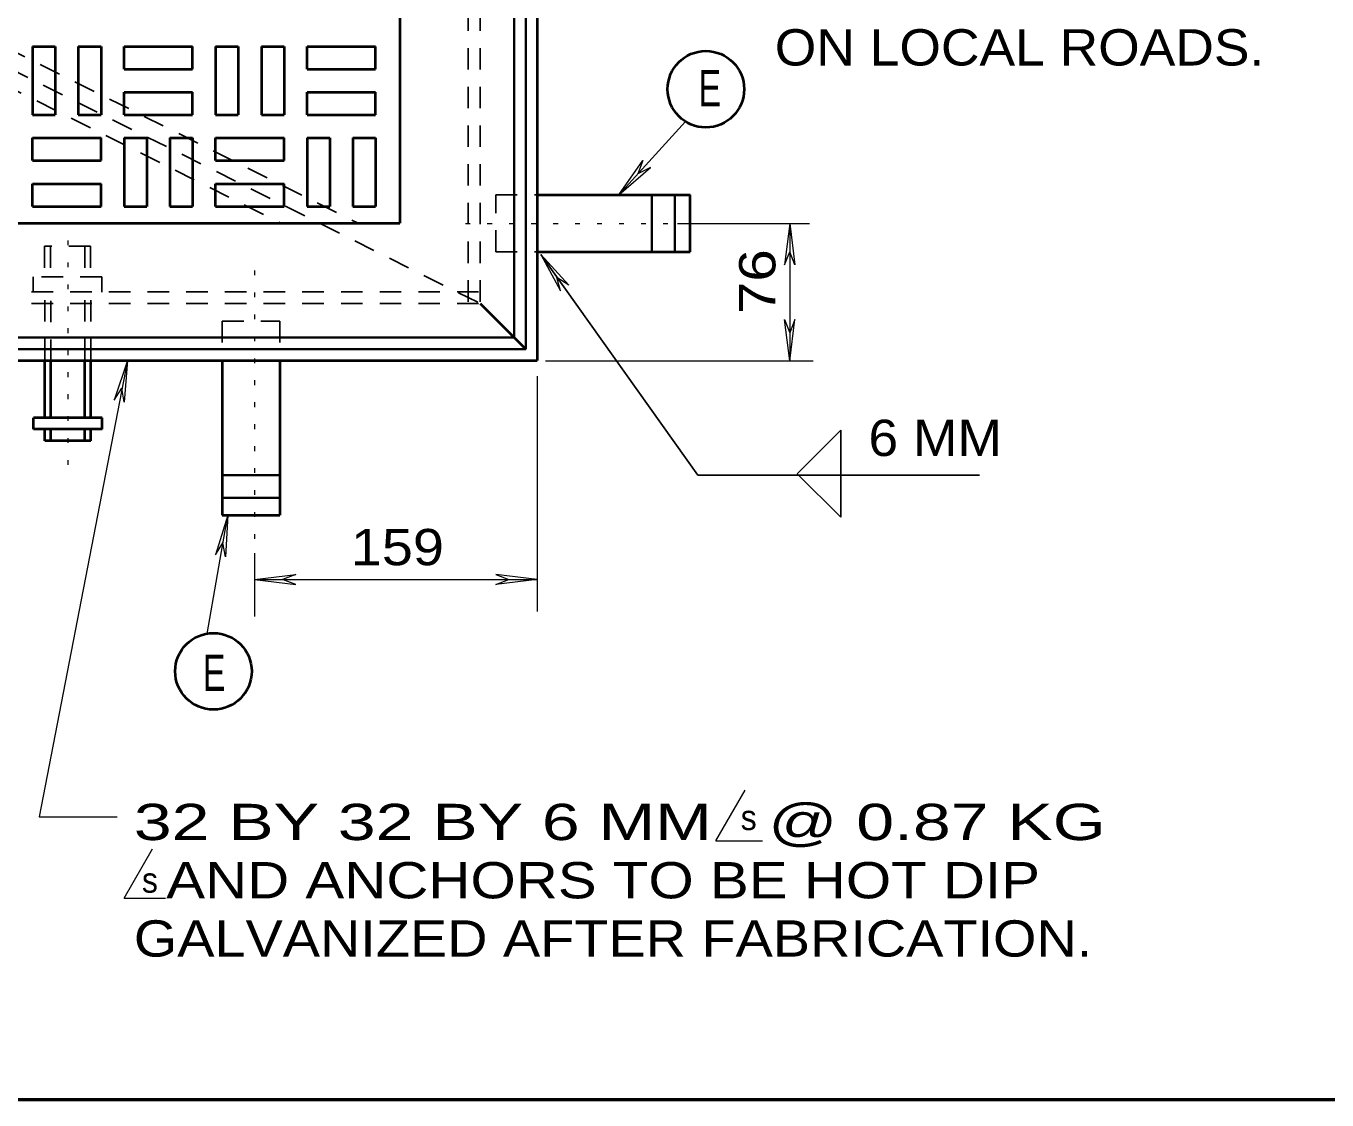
# Model space of a CAD drawing. Extents: x 312583 to 312854, y 144419 to 144597.
# Drawn here: x 312714.2 to 312741.44, y 144527.44 to 144549.93 of the extents above; entities that cross this region are included whole.
import ezdxf

# ---------------------------------------------------------------- set-up
doc = ezdxf.new("R2010")
doc.units = 0
doc.header["$LTSCALE"] = 0.3
doc.linetypes.add('DOTTED', pattern=[1.5, 0.3, -1.2])
doc.linetypes.add('SHORT_DASHED', pattern=[2.7, 1.5, -1.2])
doc.layers.add('1', color=7, linetype='Continuous', lineweight=40)
doc.layers.add('2', color=7, linetype='Continuous', lineweight=13)

msp = doc.modelspace()

# ---------------------------------------------------------------- linework, layer by layer
at = {"layer": '1', "linetype": 'SHORT_DASHED', "lineweight": 25}
for p, q in [((312689.2049, 144561.3686), (312723.7049, 144544.1186)), ((312707.2522, 144552.7436), (312721.1519, 144545.7976)), ((312723.4595, 144552.7053), (312723.4595, 144544.1186)), ((312706.4549, 144552.3449), (312719.5419, 144545.7976)), ((312724.0345, 144545.1996), (312724.0345, 144546.3956)), ((312724.0345, 144546.3956), (312724.9009, 144546.3956)), ((312715.5475, 144545.3146), (312714.5892, 144545.3146)), ((312714.5892, 144545.3146), (312714.5892, 144544.6783)), ((312714.7119, 144545.3146), (312714.7119, 144544.6783)), ((312715.4325, 144545.3146), (312715.4325, 144544.6783)), ((312715.5475, 144545.3146), (312715.5475, 144544.6783)), ((312724.0345, 144545.1996), (312724.9009, 144545.1996)), ((312714.3515, 144544.6783), (312714.3515, 144544.3563)), ((312715.7852, 144544.6783), (312714.3515, 144544.6783)), ((312715.7852, 144544.6783), (312715.7852, 144544.3563)), ((312689.2049, 144544.3639), (312723.7049, 144544.3639)), ((312714.5969, 144542.9303), (312714.5969, 144544.3639)), ((312714.7195, 144542.9149), (312714.7195, 144544.3639)), ((312715.4325, 144542.9303), (312715.4325, 144544.3639)), ((312715.5552, 144542.9303), (312715.5552, 144544.3639)), ((312718.3075, 144543.7506), (312719.5112, 144543.7506)), ((312718.3075, 144543.7506), (312718.3075, 144542.9149)), ((312719.5112, 144543.7506), (312719.5112, 144542.9303))]:
    msp.add_line(p, q, dxfattribs=at)
at = {"layer": '1'}
for p, q in [((312722.0259, 144559.6973), (312722.0259, 144545.7976)), ((312714.3362, 144549.5006), (312714.3362, 144548.0669)), ((312714.3362, 144549.5006), (312714.8115, 144549.5006)), ((312714.8115, 144549.5006), (312714.8115, 144548.0669)), ((312715.2945, 144549.5006), (312715.2945, 144548.0669)), ((312715.2945, 144549.5006), (312715.7699, 144549.5006)), ((312715.7699, 144549.5006), (312715.7699, 144548.0669)), ((312716.2529, 144549.5006), (312717.6865, 144549.5006)), ((312716.2529, 144549.0253), (312716.2529, 144549.5006)), ((312717.6865, 144549.0253), (312717.6865, 144549.5006)), ((312718.1695, 144549.5006), (312718.1695, 144548.0669)), ((312718.1695, 144549.5006), (312718.6449, 144549.5006)), ((312718.6449, 144549.5006), (312718.6449, 144548.0669)), ((312719.1279, 144549.5006), (312719.1279, 144548.0669)), ((312719.1279, 144549.5006), (312719.6032, 144549.5006)), ((312719.6032, 144549.5006), (312719.6032, 144548.0669)), ((312720.0862, 144549.5006), (312721.5199, 144549.5006)), ((312720.0862, 144549.0253), (312720.0862, 144549.5006)), ((312721.5199, 144549.0253), (312721.5199, 144549.5006)), ((312716.2529, 144549.0253), (312717.6865, 144549.0253)), ((312720.0862, 144549.0253), (312721.5199, 144549.0253)), ((312716.2529, 144548.5423), (312717.6865, 144548.5423)), ((312716.2529, 144548.0669), (312716.2529, 144548.5423)), ((312717.6865, 144548.0669), (312717.6865, 144548.5423)), ((312720.0862, 144548.5423), (312721.5199, 144548.5423)), ((312720.0862, 144548.0669), (312720.0862, 144548.5423)), ((312721.5199, 144548.0669), (312721.5199, 144548.5423)), ((312714.3362, 144548.0669), (312714.8115, 144548.0669)), ((312715.2945, 144548.0669), (312715.7699, 144548.0669)), ((312716.2529, 144548.0669), (312717.6865, 144548.0669)), ((312718.1695, 144548.0669), (312718.6449, 144548.0669)), ((312719.1279, 144548.0669), (312719.6032, 144548.0669)), ((312720.0862, 144548.0669), (312721.5199, 144548.0669)), ((312714.3362, 144547.5839), (312715.7699, 144547.5839)), ((312714.3362, 144547.1086), (312714.3362, 144547.5839)), ((312715.7699, 144547.1086), (312715.7699, 144547.5839)), ((312716.2529, 144547.5839), (312716.2529, 144546.1503)), ((312716.2529, 144547.5839), (312716.7282, 144547.5839)), ((312716.7282, 144547.5839), (312716.7282, 144546.1503)), ((312717.2112, 144547.5839), (312717.2112, 144546.1503)), ((312717.2112, 144547.5839), (312717.6865, 144547.5839)), ((312717.6865, 144547.5839), (312717.6865, 144546.1503)), ((312718.1695, 144547.5839), (312719.6032, 144547.5839)), ((312718.1695, 144547.1086), (312718.1695, 144547.5839)), ((312719.6032, 144547.1086), (312719.6032, 144547.5839)), ((312720.0862, 144547.5839), (312720.0862, 144546.1503)), ((312720.0862, 144547.5839), (312720.5615, 144547.5839)), ((312720.5615, 144547.5839), (312720.5615, 144546.1503)), ((312721.0445, 144547.5839), (312721.0445, 144546.1503)), ((312721.0445, 144547.5839), (312721.5199, 144547.5839)), ((312721.5199, 144547.5839), (312721.5199, 144546.1503)), ((312714.3362, 144547.1086), (312715.7699, 144547.1086)), ((312718.1695, 144547.1086), (312719.6032, 144547.1086)), ((312714.3362, 144546.6256), (312715.7699, 144546.6256)), ((312714.3362, 144546.1503), (312714.3362, 144546.6256)), ((312715.7699, 144546.1503), (312715.7699, 144546.6256)), ((312718.1695, 144546.6256), (312719.6032, 144546.6256)), ((312718.1695, 144546.1503), (312718.1695, 144546.6256)), ((312719.6032, 144546.1503), (312719.6032, 144546.6256)), ((312724.9009, 144546.3956), (312728.1055, 144546.3956)), ((312728.1055, 144545.1996), (312728.1055, 144546.3956)), ((312714.3362, 144546.1503), (312715.7699, 144546.1503)), ((312716.2529, 144546.1503), (312716.7282, 144546.1503)), ((312717.2112, 144546.1503), (312717.6865, 144546.1503)), ((312718.1695, 144546.1503), (312719.6032, 144546.1503)), ((312720.0862, 144546.1503), (312720.5615, 144546.1503)), ((312721.0445, 144546.1503), (312721.5199, 144546.1503)), ((312690.8762, 144545.7976), (312722.0259, 144545.7976)), ((312724.9009, 144545.1996), (312728.1055, 144545.1996)), ((312723.7049, 144544.1186), (312724.6632, 144543.1603)), ((312688.0012, 144542.9226), (312724.9009, 144542.9226)), ((312714.5969, 144541.7266), (312714.5969, 144542.9303)), ((312714.7195, 144541.7266), (312714.7195, 144542.9149)), ((312715.4325, 144541.7266), (312715.4325, 144542.9303)), ((312715.5552, 144541.7266), (312715.5552, 144542.9149)), ((312718.3075, 144542.9149), (312718.3075, 144539.6873)), ((312719.5112, 144542.9149), (312719.5112, 144539.6873)), ((312715.7929, 144541.7266), (312714.3592, 144541.7266)), ((312714.3592, 144541.4889), (312714.3592, 144541.7266)), ((312715.7929, 144541.4889), (312715.7929, 144541.7266)), ((312715.7929, 144541.4889), (312714.3592, 144541.4889)), ((312714.5969, 144541.2436), (312714.5969, 144541.4889)), ((312714.7195, 144541.2436), (312714.7195, 144541.4889)), ((312715.4325, 144541.2436), (312715.4325, 144541.4889)), ((312715.5552, 144541.2436), (312715.5552, 144541.4889)), ((312715.5552, 144541.2436), (312714.5969, 144541.2436)), ((312718.3075, 144539.6873), (312719.5112, 144539.6873))]:
    msp.add_line(p, q, dxfattribs=at)
at = {"layer": '1', "lineweight": 35}
for p, q in [((312724.4179, 144552.4906), (312724.4179, 144543.4056)), ((312727.3005, 144546.3956), (312727.3005, 144545.1996)), ((312727.7835, 144546.3956), (312727.7835, 144545.1996)), ((312688.4842, 144543.4056), (312724.4179, 144543.4056)), ((312688.2465, 144543.1603), (312724.6632, 144543.1603)), ((312718.3075, 144540.5229), (312719.5112, 144540.5229)), ((312718.3075, 144540.0476), (312719.5112, 144540.0476))]:
    msp.add_line(p, q, dxfattribs=at)
at = {"layer": '1', "linetype": 'DOTTED', "lineweight": 13}
for p, q in [((312723.3982, 144545.7899), (312727.8372, 144545.7899)), ((312715.0799, 144540.7376), (312715.0799, 144545.4756))]:
    msp.add_line(p, q, dxfattribs=at)
at = {"layer": '1', "lineweight": 53}
msp.add_line((312742.1369, 144527.439), (312675.4374, 144527.439), dxfattribs=at)
at = {"layer": '1'}
msp.add_lwpolyline([(312688.0012, 144562.5723), (312724.9009, 144562.5723), (312724.9009, 144542.9226)], dxfattribs=at)
at = {"layer": '1', "lineweight": 35}
msp.add_lwpolyline([(312688.2465, 144562.3269), (312724.6632, 144562.3269), (312724.6632, 144543.1603)], dxfattribs=at)
at = {"layer": '1', "linetype": 'SHORT_DASHED', "lineweight": 25}
for points in [[(312689.2049, 144561.3686), (312689.2049, 144544.1186), (312723.7049, 144544.1186)], [(312723.7049, 144561.3686), (312723.7049, 144552.7053), (312723.7049, 144544.1186)]]:
    msp.add_lwpolyline(points, dxfattribs=at)
at = {"layer": '2'}
for p, q in [((312728.0068, 144547.927), (312726.6105, 144546.3956)), ((312726.6105, 144546.3956), (312727.1165, 144547.1086)), ((312727.1165, 144547.1086), (312727.0092, 144546.8326)), ((312726.6105, 144546.3956), (312727.2775, 144546.9629)), ((312727.2775, 144546.9629), (312727.0092, 144546.8326)), ((312727.8372, 144545.7899), (312730.6049, 144545.7899)), ((312730.1909, 144545.7899), (312730.0835, 144544.9236)), ((312730.1909, 144545.7899), (312730.1909, 144542.9149)), ((312730.1909, 144545.7899), (312730.2982, 144544.9236)), ((312730.0835, 144544.9236), (312730.1909, 144545.1996)), ((312730.2982, 144544.9236), (312730.1909, 144545.1996)), ((312724.9775, 144545.1459), (312725.3915, 144544.3793)), ((312724.9775, 144545.1459), (312725.5679, 144544.5019)), ((312725.3915, 144544.3793), (312725.3149, 144544.6629)), ((312725.5679, 144544.5019), (312725.3149, 144544.6629)), ((312730.0835, 144543.7813), (312730.1909, 144543.5053)), ((312730.1909, 144542.9149), (312730.0835, 144543.7813)), ((312730.2982, 144543.7813), (312730.1909, 144543.5053)), ((312730.1909, 144542.9149), (312730.2982, 144543.7813)), ((312716.3219, 144542.9226), (312714.4784, 144533.37)), ((312716.3219, 144542.9226), (312716.0441, 144542.095)), ((312716.3219, 144542.9226), (312716.2545, 144542.0523)), ((312725.0772, 144542.9149), (312730.6815, 144542.9149)), ((312724.9009, 144542.5929), (312724.9009, 144537.6709)), ((312716.0441, 144542.095), (312716.2043, 144542.3441)), ((312716.2545, 144542.0523), (312716.2043, 144542.3441)), ((312717.9932, 144537.2033), (312718.4225, 144539.6873)), ((312718.4225, 144539.6873), (312718.1695, 144538.8516)), ((312718.4225, 144539.6873), (312718.3765, 144538.8133)), ((312718.1695, 144538.8516), (312718.3229, 144539.1046)), ((312718.3765, 144538.8133), (312718.3229, 144539.1046)), ((312718.9822, 144538.8899), (312718.9822, 144537.5636)), ((312718.9822, 144538.3379), (312719.8485, 144538.4453)), ((312719.8485, 144538.4453), (312719.5725, 144538.3379)), ((312724.0345, 144538.4453), (312724.3105, 144538.3379)), ((312724.9009, 144538.3379), (312724.0345, 144538.4453)), ((312718.9822, 144538.3379), (312724.9009, 144538.3379)), ((312718.9822, 144538.3379), (312719.8485, 144538.2306)), ((312719.8485, 144538.2306), (312719.5725, 144538.3379)), ((312724.0345, 144538.2306), (312724.3105, 144538.3379)), ((312724.9009, 144538.3379), (312724.0345, 144538.2306)), ((312728.6425, 144532.8687), (312729.2558, 144533.9267)), ((312714.4784, 144533.37), (312716.109, 144533.37)), ((312716.2513, 144531.6651), (312716.8493, 144532.7001)), ((312728.6425, 144532.8687), (312729.6162, 144532.8687)), ((312716.2513, 144531.6651), (312717.1177, 144531.6651))]:
    msp.add_line(p, q, dxfattribs=at)
at = {"layer": '2', "lineweight": 25}
for p, q in [((312728.2665, 144540.5229), (312724.9775, 144545.1459)), ((312730.3442, 144540.5536), (312731.2565, 144541.4659)), ((312731.2565, 144539.6413), (312731.2565, 144541.4659)), ((312730.3442, 144540.5536), (312731.2565, 144539.6413)), ((312728.2665, 144540.5229), (312734.1622, 144540.5229))]:
    msp.add_line(p, q, dxfattribs=at)
at = {"layer": '2', "linetype": 'DOTTED'}
msp.add_line((312718.9822, 144544.8086), (312718.9822, 144538.8899), dxfattribs=at)
at = {"layer": '2', "lineweight": 40}
for centre in [(312728.4343, 144548.6046), (312718.1235, 144536.4155)]:
    msp.add_circle(centre, 0.8012, dxfattribs=at)

# ---------------------------------------------------------------- texts
at = {"layer": '1', "width": 1.1}
msp.add_text('ON LOCAL ROADS.', height=0.76, dxfattribs=at).set_placement((312729.8765, 144549.1009))
at = {"layer": '2'}
for s, height, width, p in [('E', 0.76, 0.7, (312728.279, 144548.2442)), ('6 MM', 0.76, 1.1, (312731.8376, 144540.9236)), ('159 ', 0.76, 1.15, (312720.9998, 144538.6369)), ('E', 0.76, 0.7, (312717.9012, 144536.0063)), ('32 BY 32 BY 6 MM   @ 0.87 KG', 0.76, 1.4, (312716.4576, 144532.881)), ('s', 0.5261, 0.95, (312729.1638, 144533.091)), ('  AND ANCHORS TO BE HOT DIP', 0.76, 1.2, (312716.4576, 144531.661)), ('s', 0.5261, 0.95, (312716.627, 144531.7801)), ('GALVANIZED AFTER FABRICATION.', 0.76, 1.15, (312716.4576, 144530.441))]:
    msp.add_text(s, height=height, dxfattribs=dict(at, width=width)).set_placement(p)
at = {"layer": '2', "width": 1.2}
msp.add_text('76 ', height=0.76, rotation=90, dxfattribs=at).set_placement((312729.8896, 144543.8972))

doc.saveas('drawing.dxf')
